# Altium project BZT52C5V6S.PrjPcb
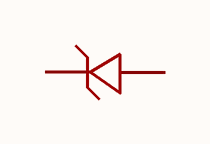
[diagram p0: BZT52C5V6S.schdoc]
1 sheet, 1 parts. Net scope: global (net labels, ports and power ports of the same name join across sheets).

## Sheet BZT52C5V6S.schdoc
size 127 x 101 mm

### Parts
ZD?  bzt52c5v6s_c22612  [SOD-323_L1.8-W1.3-LS2.5-RD]  (value not drawn)

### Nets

Not connected (* = marked no-connect by the designer): ZD? 1(K) 2(A)

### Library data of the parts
ZD? = bzt52c5v6s_c22612: 二极管配置:1个独立式;稳压值(标称值):5.6V;稳压值(范围):5.2V~6V;耗散功率(Pd):200mW;; Manufacturer: CJ(江苏长电/长晶); AddInBom: yes; ModelId: db63db13d9e342eb939127d413d6200b; ModelTransform: 104.3305,51.181,0,0,0,0,0,-0.004,0; Diode Configuration: 1个独立式; Zener Voltage(Nom): 5.6V; Reverse Leakage Current (Ir): 1uA; Pd - Power Dissipation: 200mW; Impedance(Zzt): 40Ω; Impedance(Zzk): 400Ω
